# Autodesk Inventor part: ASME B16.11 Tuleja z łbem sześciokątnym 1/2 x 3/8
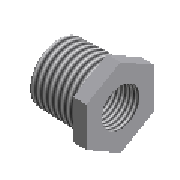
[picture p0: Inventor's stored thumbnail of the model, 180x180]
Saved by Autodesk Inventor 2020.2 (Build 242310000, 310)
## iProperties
Manager: www.cadconsulting.pl
Company: Fabian Stasiak CAD Consulting
NAME: PIPING: ASME B16.11 Hex Head Bushing
DATA: <meta><inlinegroups number="1" deflen="1.4224"></inlinegroups><connections number="2"></connections><angles><a>3.14159265358979</a></angles></meta>
IsCustomPart: 0
Created: 2014-02
Part Number: ASME B16.11 Tuleja z łbem sześciokątnym 1/2 x 3/8
Material: Stal
Description: Tuleja z łbem sześciokątnym
Document SubType Name: Modeling
Standard: ASME B16.11
Designer: F.Stasiak
Standard Revision: 2005
Standards Organization: ANSI
Language: pl-PL
Size Designation: 1/2 x 3/8
Categories: <MemberInstance><Categories><Category DisplayName="Rury cienko- i grubościenne" InternalName="4347fa0f-2144-441d-94cd-e3e15c92b736" Mnemonic="TUBEANDPIPE"><Cate
Density: 1 g/cm^3
Appearance: Płyta
Catalog Web Link: www.expertbooks.pl
Author: F.Stasiak
Subject: Zbiór ćwiczeń. Autodesk Inventor 2020. Kurs Professional
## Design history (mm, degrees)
sketch "Sketch1"
  geometry: L1 (0, 0)-(-19.05, 0); L2 (-19.05, 0)-(-19.05, 7.399); L3 (-19.05, 11.176)-(-14.224, 11.176); L4 (-14.224, 11.176)-(-14.224, 10.767); L5 (-14.224, 10.767)-(-13.111, 10.767); L6 (-13.111, 10.767)-(0, 10.358); L7 (0, 10.358)-(0, 6.803); L8 (0, 6.803)-(-19.05, 7.399); L9 (0, 6.803)-(0, 0); L10 (-19.05, 11.176)-(-19.05, 7.399); L11 (-13.111, 10.767)-(-13.111, 0); L12 (-8.128, 10.612)-(-8.128, 0)
  constraints: 24 end point, 5 parallel, 5 perpendicular, 3 point on line, 1 horizontal
  dimensions: "d0" = 1.78991 deg angle of L1 L8; "d1" = 14.79728 diameter of L2.end L1 (= MD); "d2" = 1.11298 distance of L4.end L5.end (= L); "d3" = 14.224 distance between parallel lines of L9 L4 (= A); "d4" = 4.826 distance between parallel lines of L4 L10 (= G); "d5" = 22.352 diameter of L3 L1 (= F1); "d9" = 8.128 distance between parallel lines of L9 L12 (= Lh); "d10" = 21.22348 diameter of L12.start L1 (= Dh)
revolve "Revolve1" sketch "Sketch1" stored, may be unused: angle "d8" = 90 deg
sketch "Sketch2"
  geometry: L1 (-11.176, 6.452)-(0, 12.905); L2 (0, 12.905)-(11.176, 6.452); L3 (11.176, 6.452)-(11.176, -6.452); L4 (11.176, -6.452)-(0, -12.905); L5 (0, -12.905)-(-11.176, -6.452); L6 (-11.176, -6.452)-(-11.176, 6.452); 4 further points
  constraints: 12 end point, 1 coincident, 1 horizontal alignment, 1 midpoint, 1 vertical, 12 other
extrude "Extrude1" join sketch "Sketch2" distance "d6" = 4.826 (= G); taper "d7" = 0 deg
workpoint "Work Point1"
workaxis "Work Axis1"
workpoint "Work Point2"
workaxis "Work Axis2"
workpoint "Work Point3"
workpoint "Work Point4"
body "Solid1"
feature "Gwint1" dims "d11" = 25.4, "d12" = 0
feature "Gwint2" dims "d13" = 25.4, "d14" = 0
other parameters: "MD" = 14.79728 [user parameter; used in 1 equation term], "A" = 14.224 [user parameter; used in 1 equation term], "G" = 4.826 [user parameter; used in 2 equation terms], "F1" = 22.352 [user parameter; used in 1 equation term], "p" = 1.8143 [user parameter], "L" = 1.11298 [user parameter; used in 1 equation term], "Dh" = 21.22348 [user parameter; used in 1 equation term], "Lh" = 8.128 [user parameter; used in 1 equation term], "Size_Designation" = 12.345 [user parameter]
